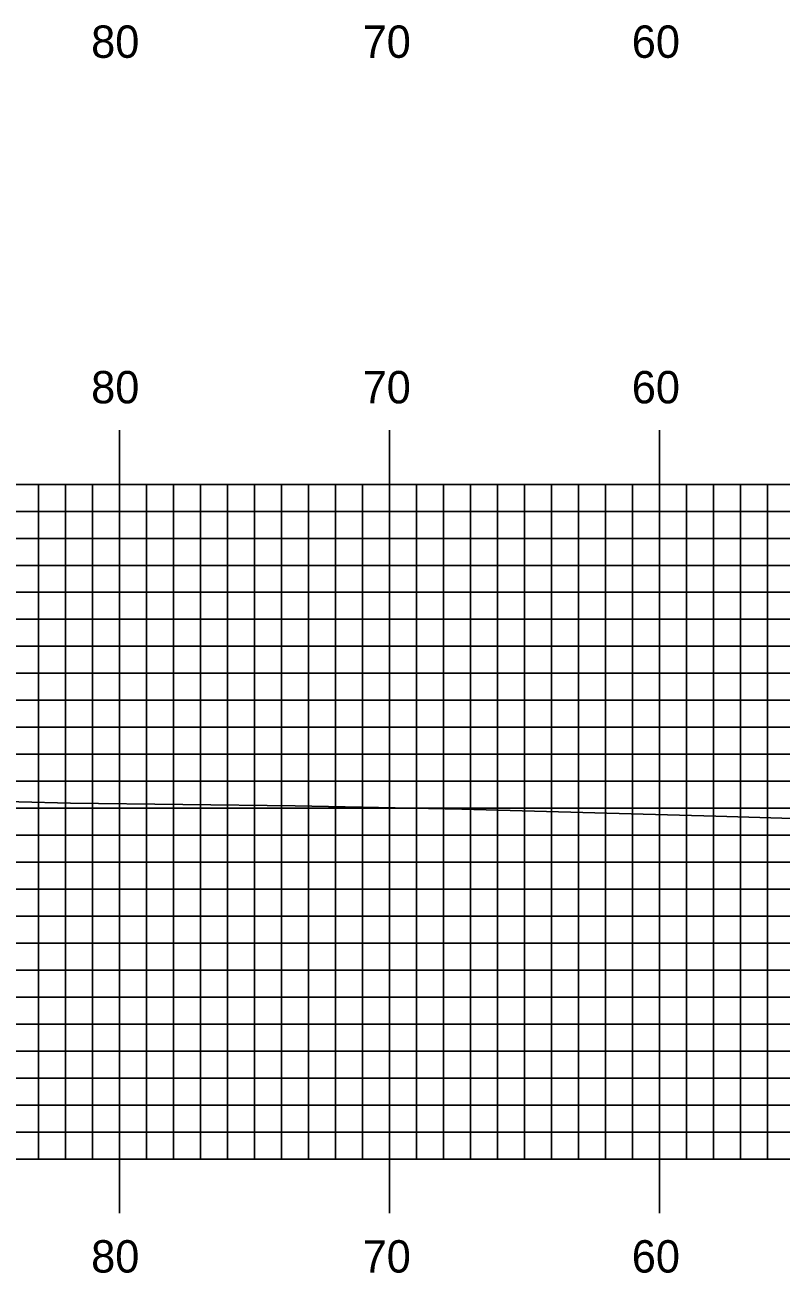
# Model space of a CAD drawing. Extents: x 1771235 to 1771579, y 442591 to 442811.
# Drawn here: x 1771317.57 to 1771345.57, y 442649.45 to 442695.68 of the extents above; entities that cross this region are included whole.
import ezdxf

# ---------------------------------------------------------------- set-up
doc = ezdxf.new("R2010")
doc.units = 0
for name, color, linetype in [('H_V ANNOTATION', 7, 'Continuous'), ('MAJOR', 7, 'Continuous'), ('MINOR', 7, 'Continuous'), ('S_Roadway_Centerline', 7, 'Continuous')]:
    doc.layers.add(name, color=color, linetype=linetype)

msp = doc.modelspace()

# ---------------------------------------------------------------- linework, layer by layer
at = {"layer": 'MAJOR'}
for p, q in [((1771321.067, 442680.669), (1771321.067, 442678.665)), ((1771331.067, 442680.669), (1771331.067, 442678.665)), ((1771341.067, 442680.669), (1771341.067, 442678.665)), ((1771261.067, 442678.665), (1771541.067, 442678.665)), ((1771261.067, 442678.665), (1771541.067, 442678.665)), ((1771321.067, 442653.665), (1771321.067, 442678.665)), ((1771331.067, 442653.665), (1771331.067, 442678.665)), ((1771341.067, 442653.665), (1771341.067, 442678.665)), ((1771261.067, 442673.665), (1771541.067, 442673.665)), ((1771261.067, 442668.665), (1771541.067, 442668.665)), ((1771261.067, 442663.665), (1771541.067, 442663.665)), ((1771261.067, 442658.665), (1771541.067, 442658.665)), ((1771261.067, 442653.665), (1771541.067, 442653.665)), ((1771261.067, 442653.665), (1771541.067, 442653.665)), ((1771321.067, 442651.661), (1771321.067, 442653.665)), ((1771331.067, 442651.661), (1771331.067, 442653.665)), ((1771341.067, 442651.661), (1771341.067, 442653.665))]:
    msp.add_line(p, q, dxfattribs=at)
at = {"layer": 'MINOR'}
for p, q in [((1771318.067, 442653.665), (1771318.067, 442678.665)), ((1771319.067, 442653.665), (1771319.067, 442678.665)), ((1771320.067, 442653.665), (1771320.067, 442678.665)), ((1771322.067, 442653.665), (1771322.067, 442678.665)), ((1771323.067, 442653.665), (1771323.067, 442678.665)), ((1771324.067, 442653.665), (1771324.067, 442678.665)), ((1771325.067, 442653.665), (1771325.067, 442678.665)), ((1771326.067, 442653.665), (1771326.067, 442678.665)), ((1771327.067, 442653.665), (1771327.067, 442678.665)), ((1771328.067, 442653.665), (1771328.067, 442678.665)), ((1771329.067, 442653.665), (1771329.067, 442678.665)), ((1771330.067, 442653.665), (1771330.067, 442678.665)), ((1771332.067, 442653.665), (1771332.067, 442678.665)), ((1771333.067, 442653.665), (1771333.067, 442678.665)), ((1771334.067, 442653.665), (1771334.067, 442678.665)), ((1771335.067, 442653.665), (1771335.067, 442678.665)), ((1771336.067, 442653.665), (1771336.067, 442678.665)), ((1771337.067, 442653.665), (1771337.067, 442678.665)), ((1771338.067, 442653.665), (1771338.067, 442678.665)), ((1771339.067, 442653.665), (1771339.067, 442678.665)), ((1771340.067, 442653.665), (1771340.067, 442678.665)), ((1771342.067, 442653.665), (1771342.067, 442678.665)), ((1771343.067, 442653.665), (1771343.067, 442678.665)), ((1771344.067, 442653.665), (1771344.067, 442678.665)), ((1771345.067, 442653.665), (1771345.067, 442678.665)), ((1771261.067, 442677.665), (1771541.067, 442677.665)), ((1771261.067, 442676.665), (1771541.067, 442676.665)), ((1771261.067, 442675.665), (1771541.067, 442675.665)), ((1771261.067, 442674.665), (1771541.067, 442674.665)), ((1771261.067, 442672.665), (1771541.067, 442672.665)), ((1771261.067, 442671.665), (1771541.067, 442671.665)), ((1771261.067, 442670.665), (1771541.067, 442670.665)), ((1771261.067, 442669.665), (1771541.067, 442669.665)), ((1771261.067, 442667.665), (1771541.067, 442667.665)), ((1771261.067, 442666.665), (1771541.067, 442666.665)), ((1771261.067, 442665.665), (1771541.067, 442665.665)), ((1771261.067, 442664.665), (1771541.067, 442664.665)), ((1771261.067, 442662.665), (1771541.067, 442662.665)), ((1771261.067, 442661.665), (1771541.067, 442661.665)), ((1771261.067, 442660.665), (1771541.067, 442660.665)), ((1771261.067, 442659.665), (1771541.067, 442659.665)), ((1771261.067, 442657.665), (1771541.067, 442657.665)), ((1771261.067, 442656.665), (1771541.067, 442656.665)), ((1771261.067, 442655.665), (1771541.067, 442655.665)), ((1771261.067, 442654.665), (1771541.067, 442654.665))]:
    msp.add_line(p, q, dxfattribs=at)
at = {"layer": 'S_Roadway_Centerline'}
msp.add_lwpolyline([(1771261.067, 442668.217), (1771270.986, 442667.868), (1771273.863, 442667.761), (1771278.882, 442667.689), (1771292.748, 442667.403), (1771296.027, 442667.372), (1771313.506, 442667.004), (1771319.254, 442666.854), (1771327.568, 442666.756), (1771333.743, 442666.634), (1771343.154, 442666.376), (1771353.348, 442666.07)], dxfattribs=at)

# ---------------------------------------------------------------- texts
at = {"layer": 'H_V ANNOTATION'}
for s, p in [('80', (1771320.018, 442694.465)), ('70', (1771330.072, 442694.465)), ('60', (1771340.04, 442694.465)), ('80', (1771320.018, 442681.665)), ('70', (1771330.072, 442681.665)), ('60', (1771340.04, 442681.665)), ('80', (1771320.018, 442649.465)), ('70', (1771330.072, 442649.465)), ('60', (1771340.04, 442649.465))]:
    msp.add_text(s, height=1.2, dxfattribs=at).set_placement(p)

doc.saveas('drawing.dxf')
